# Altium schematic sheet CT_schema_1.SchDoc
size 703 x 687 mm
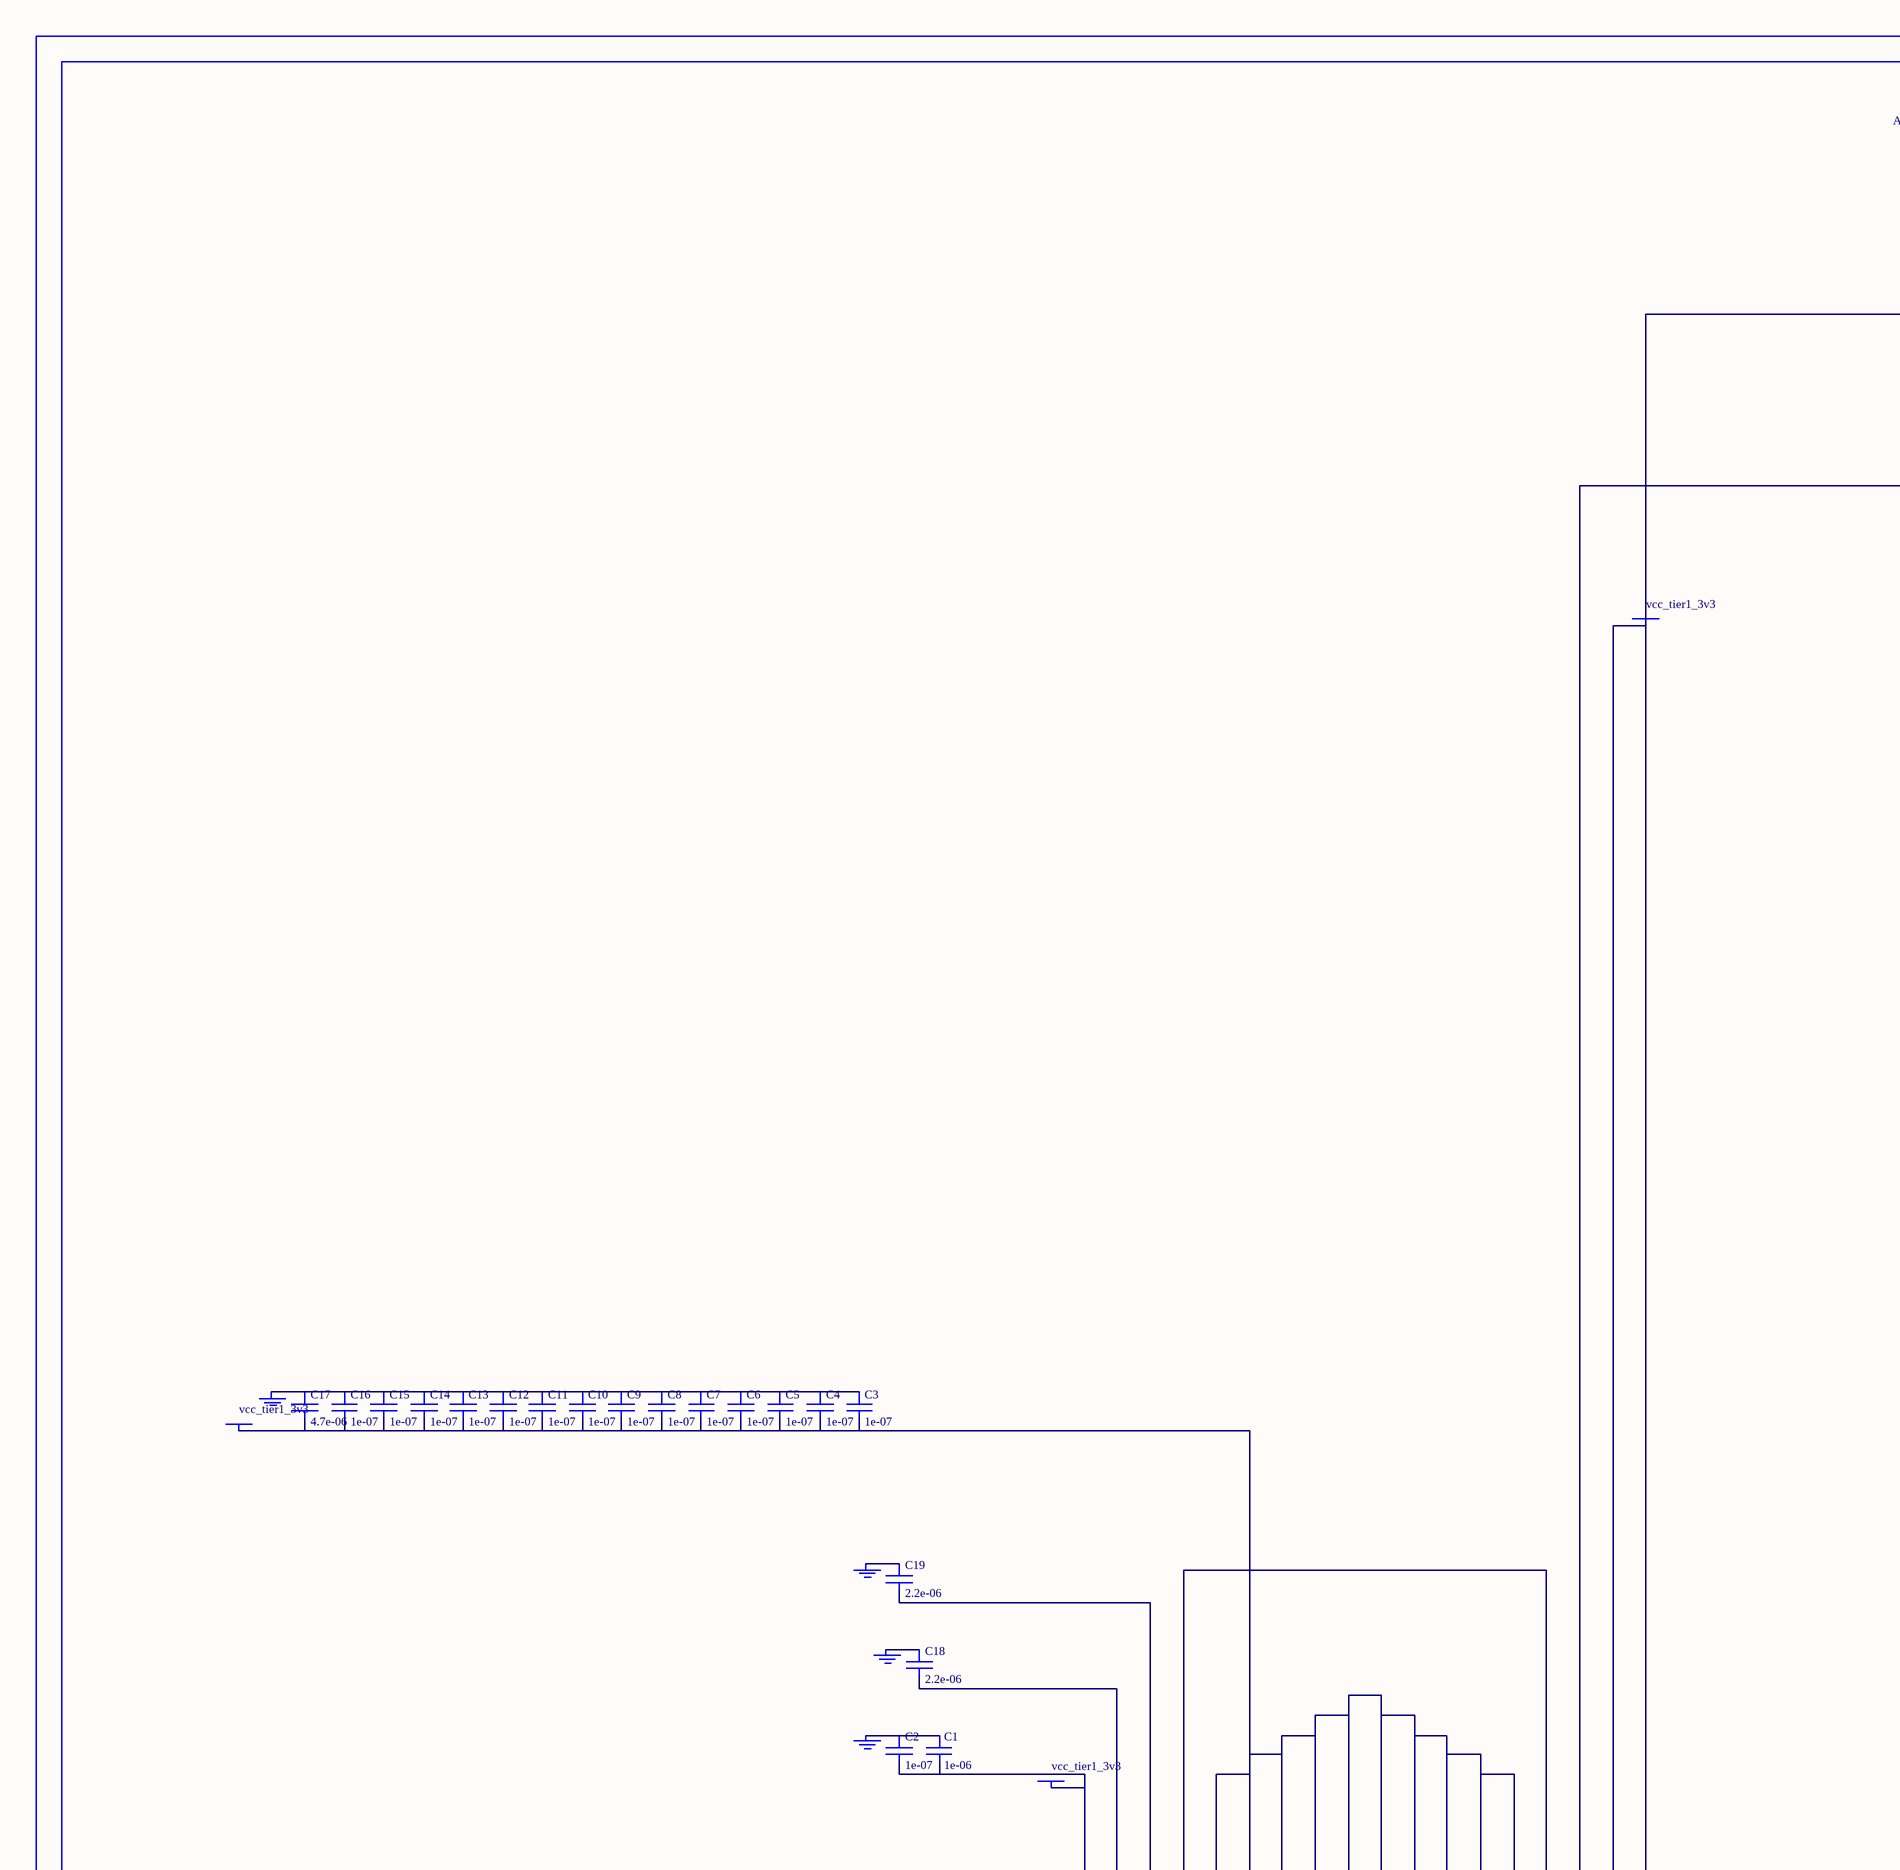
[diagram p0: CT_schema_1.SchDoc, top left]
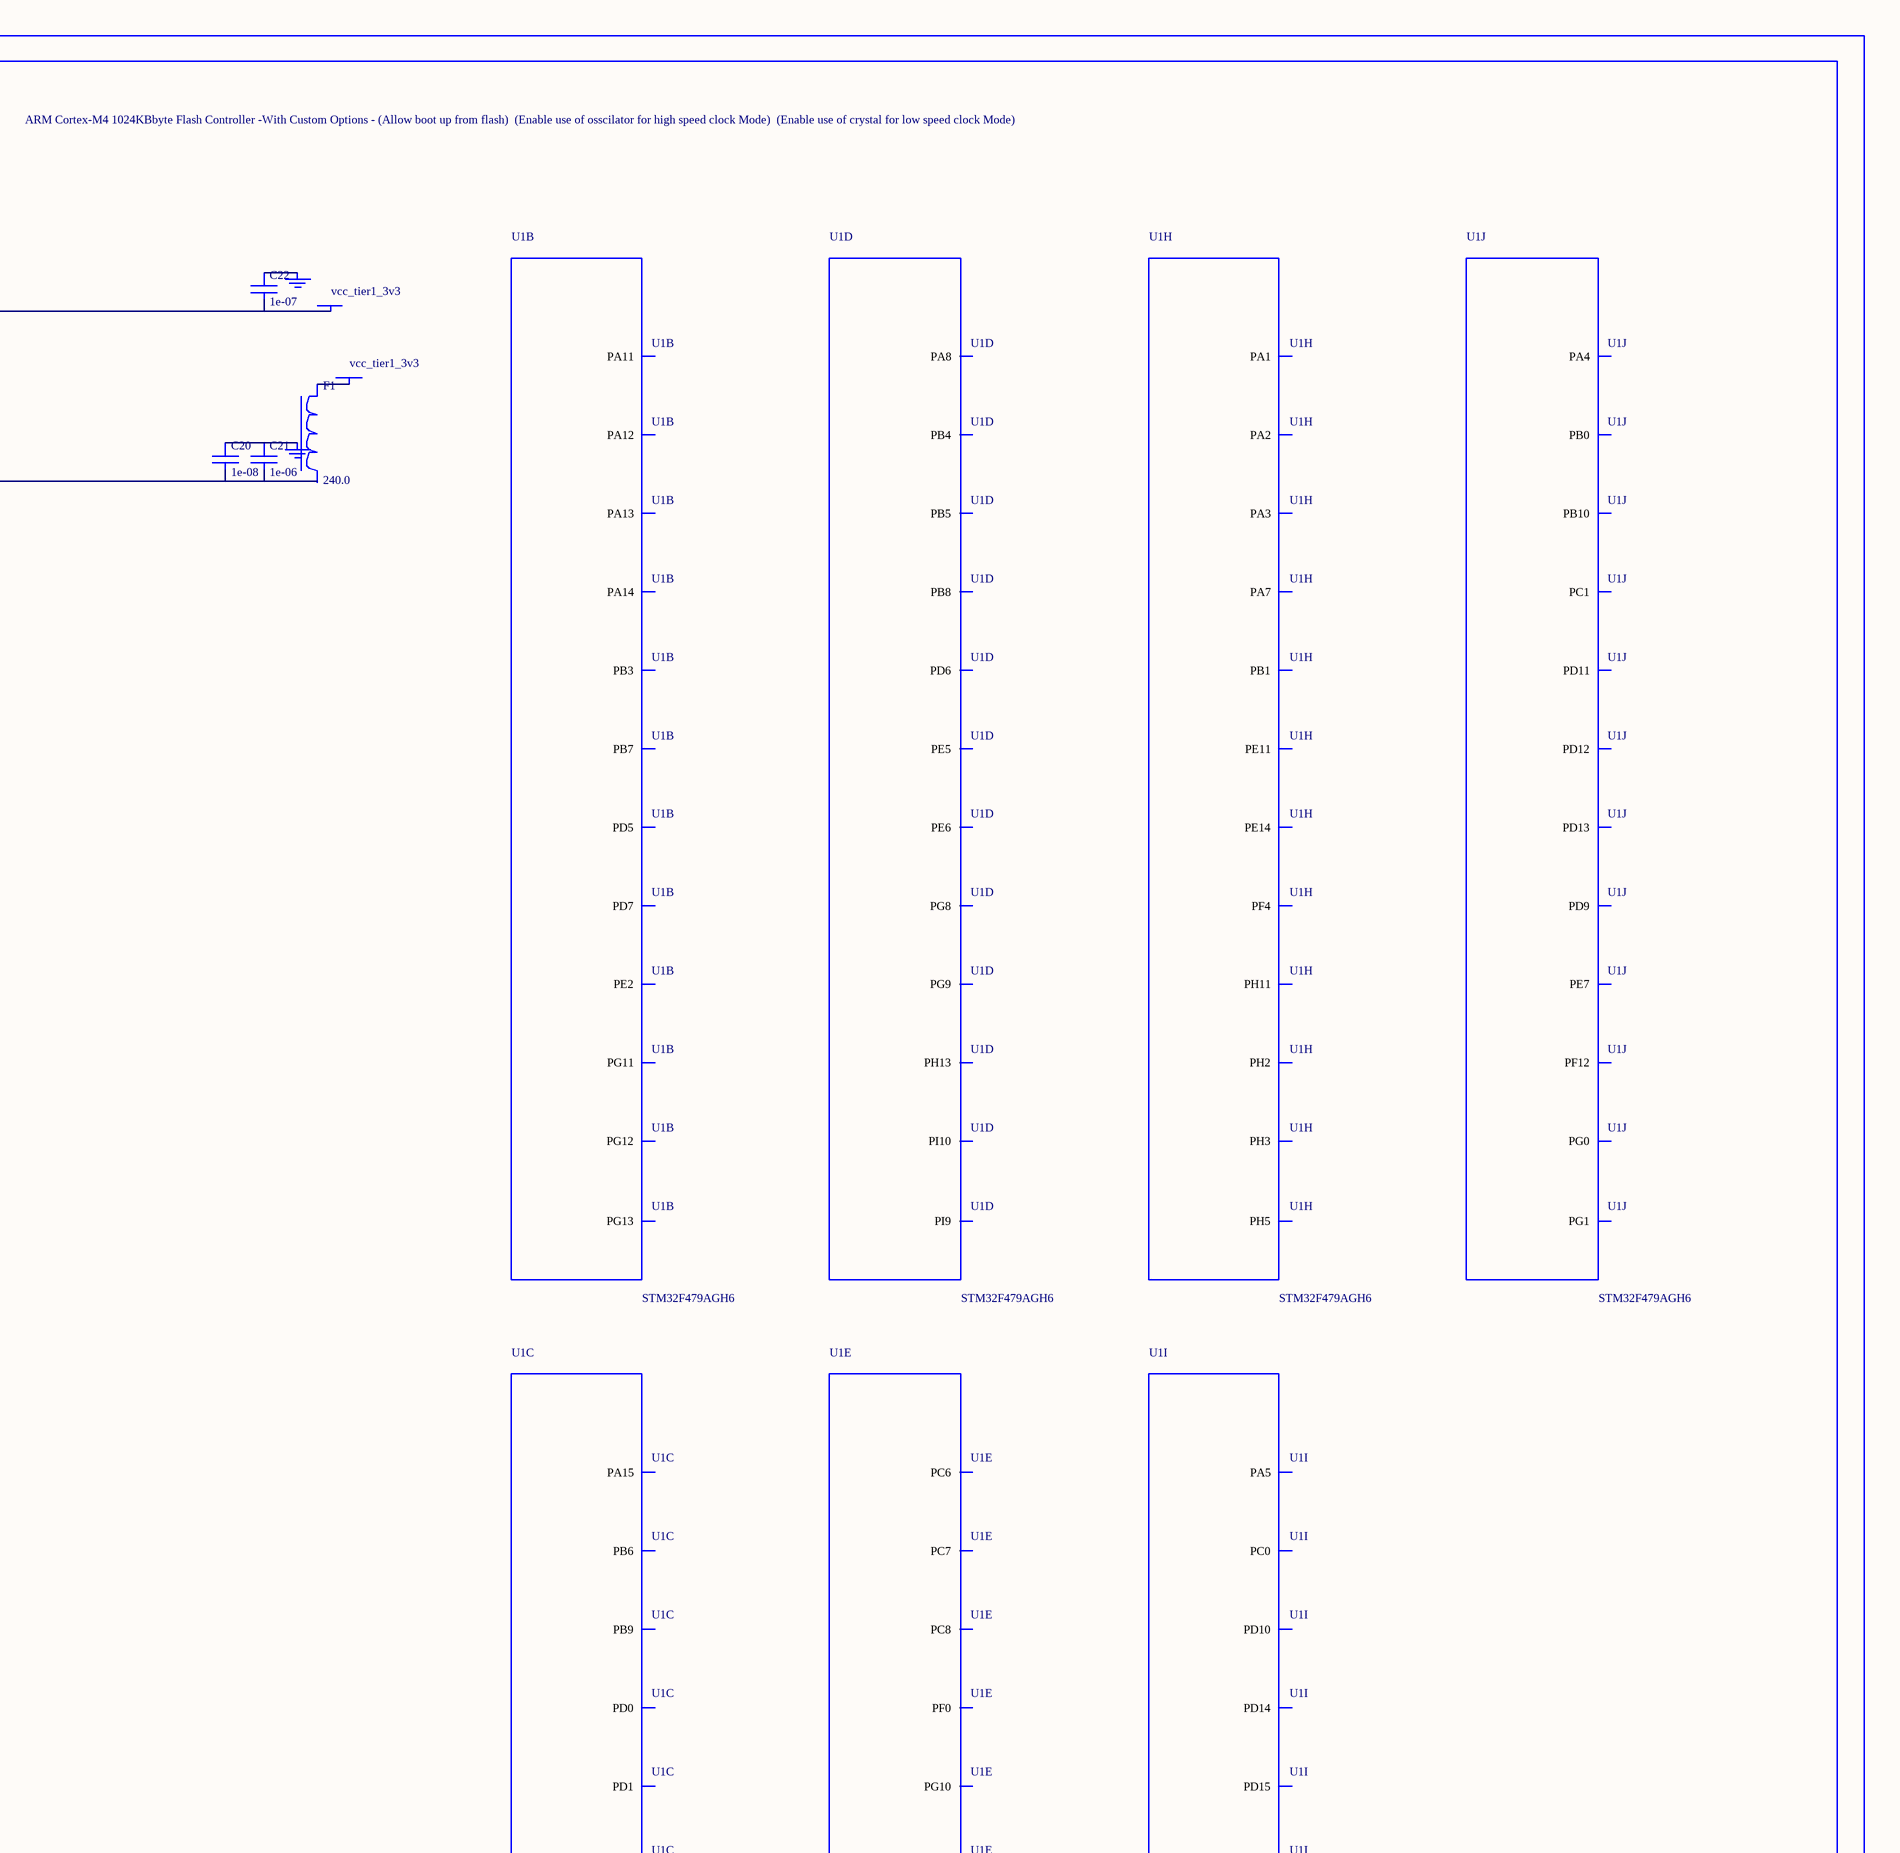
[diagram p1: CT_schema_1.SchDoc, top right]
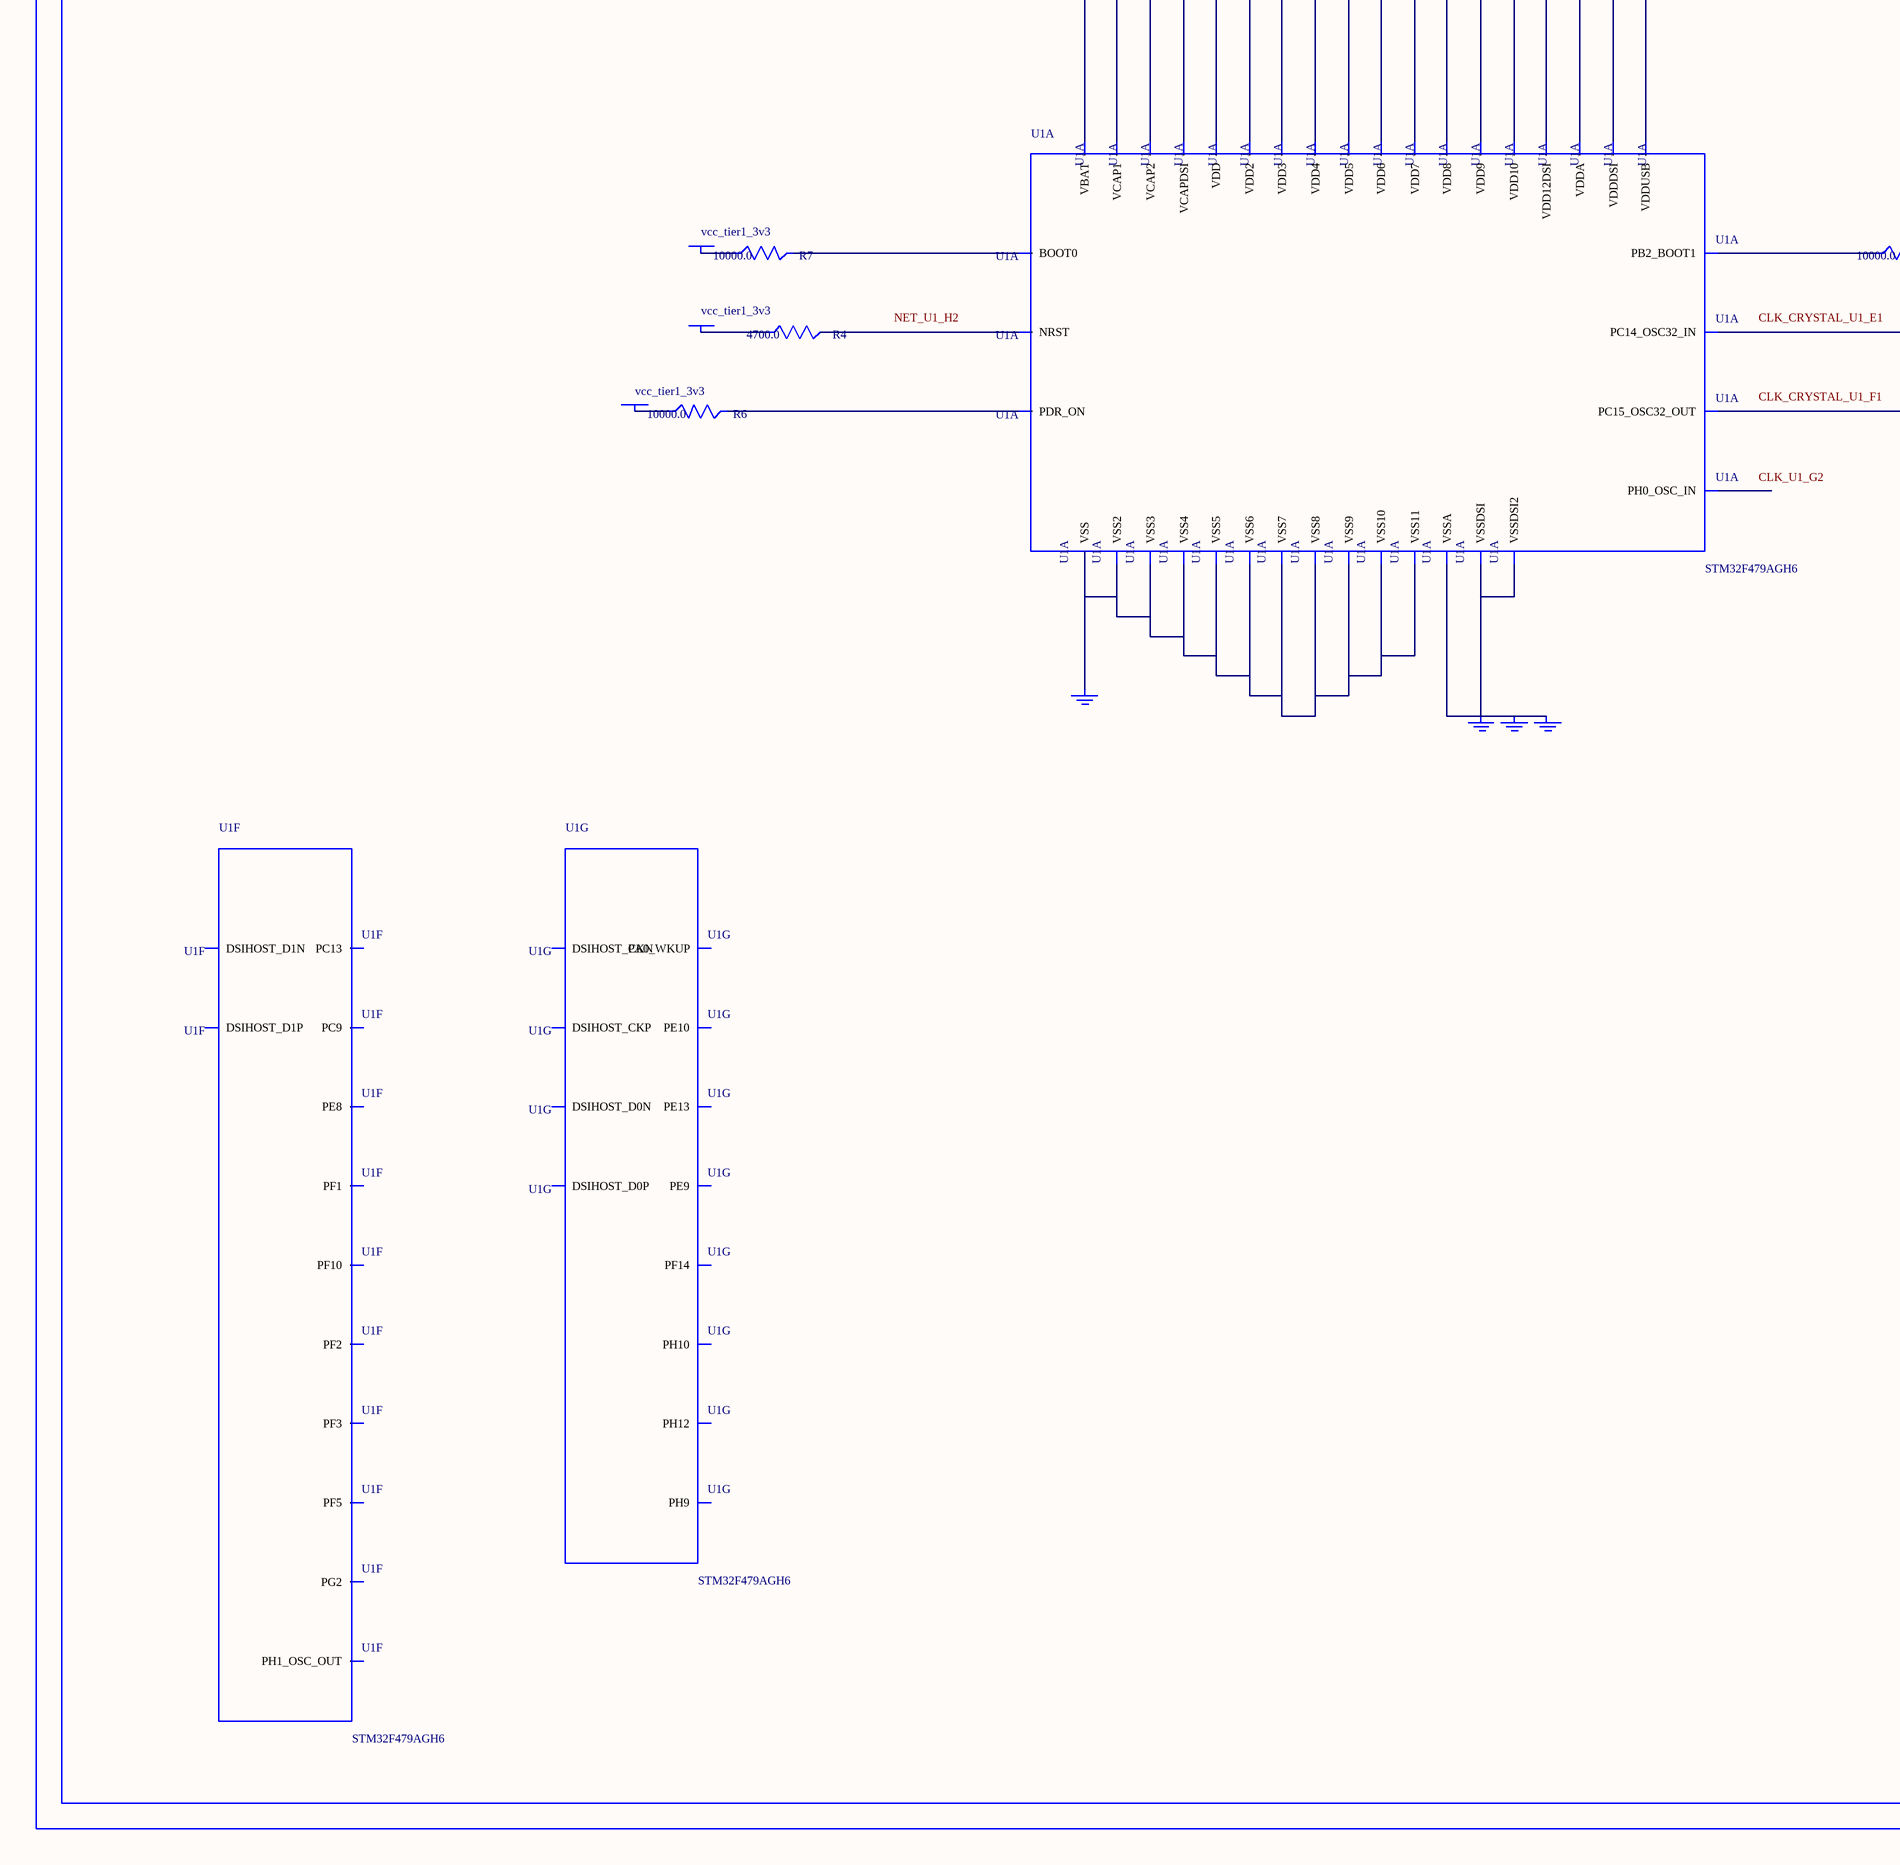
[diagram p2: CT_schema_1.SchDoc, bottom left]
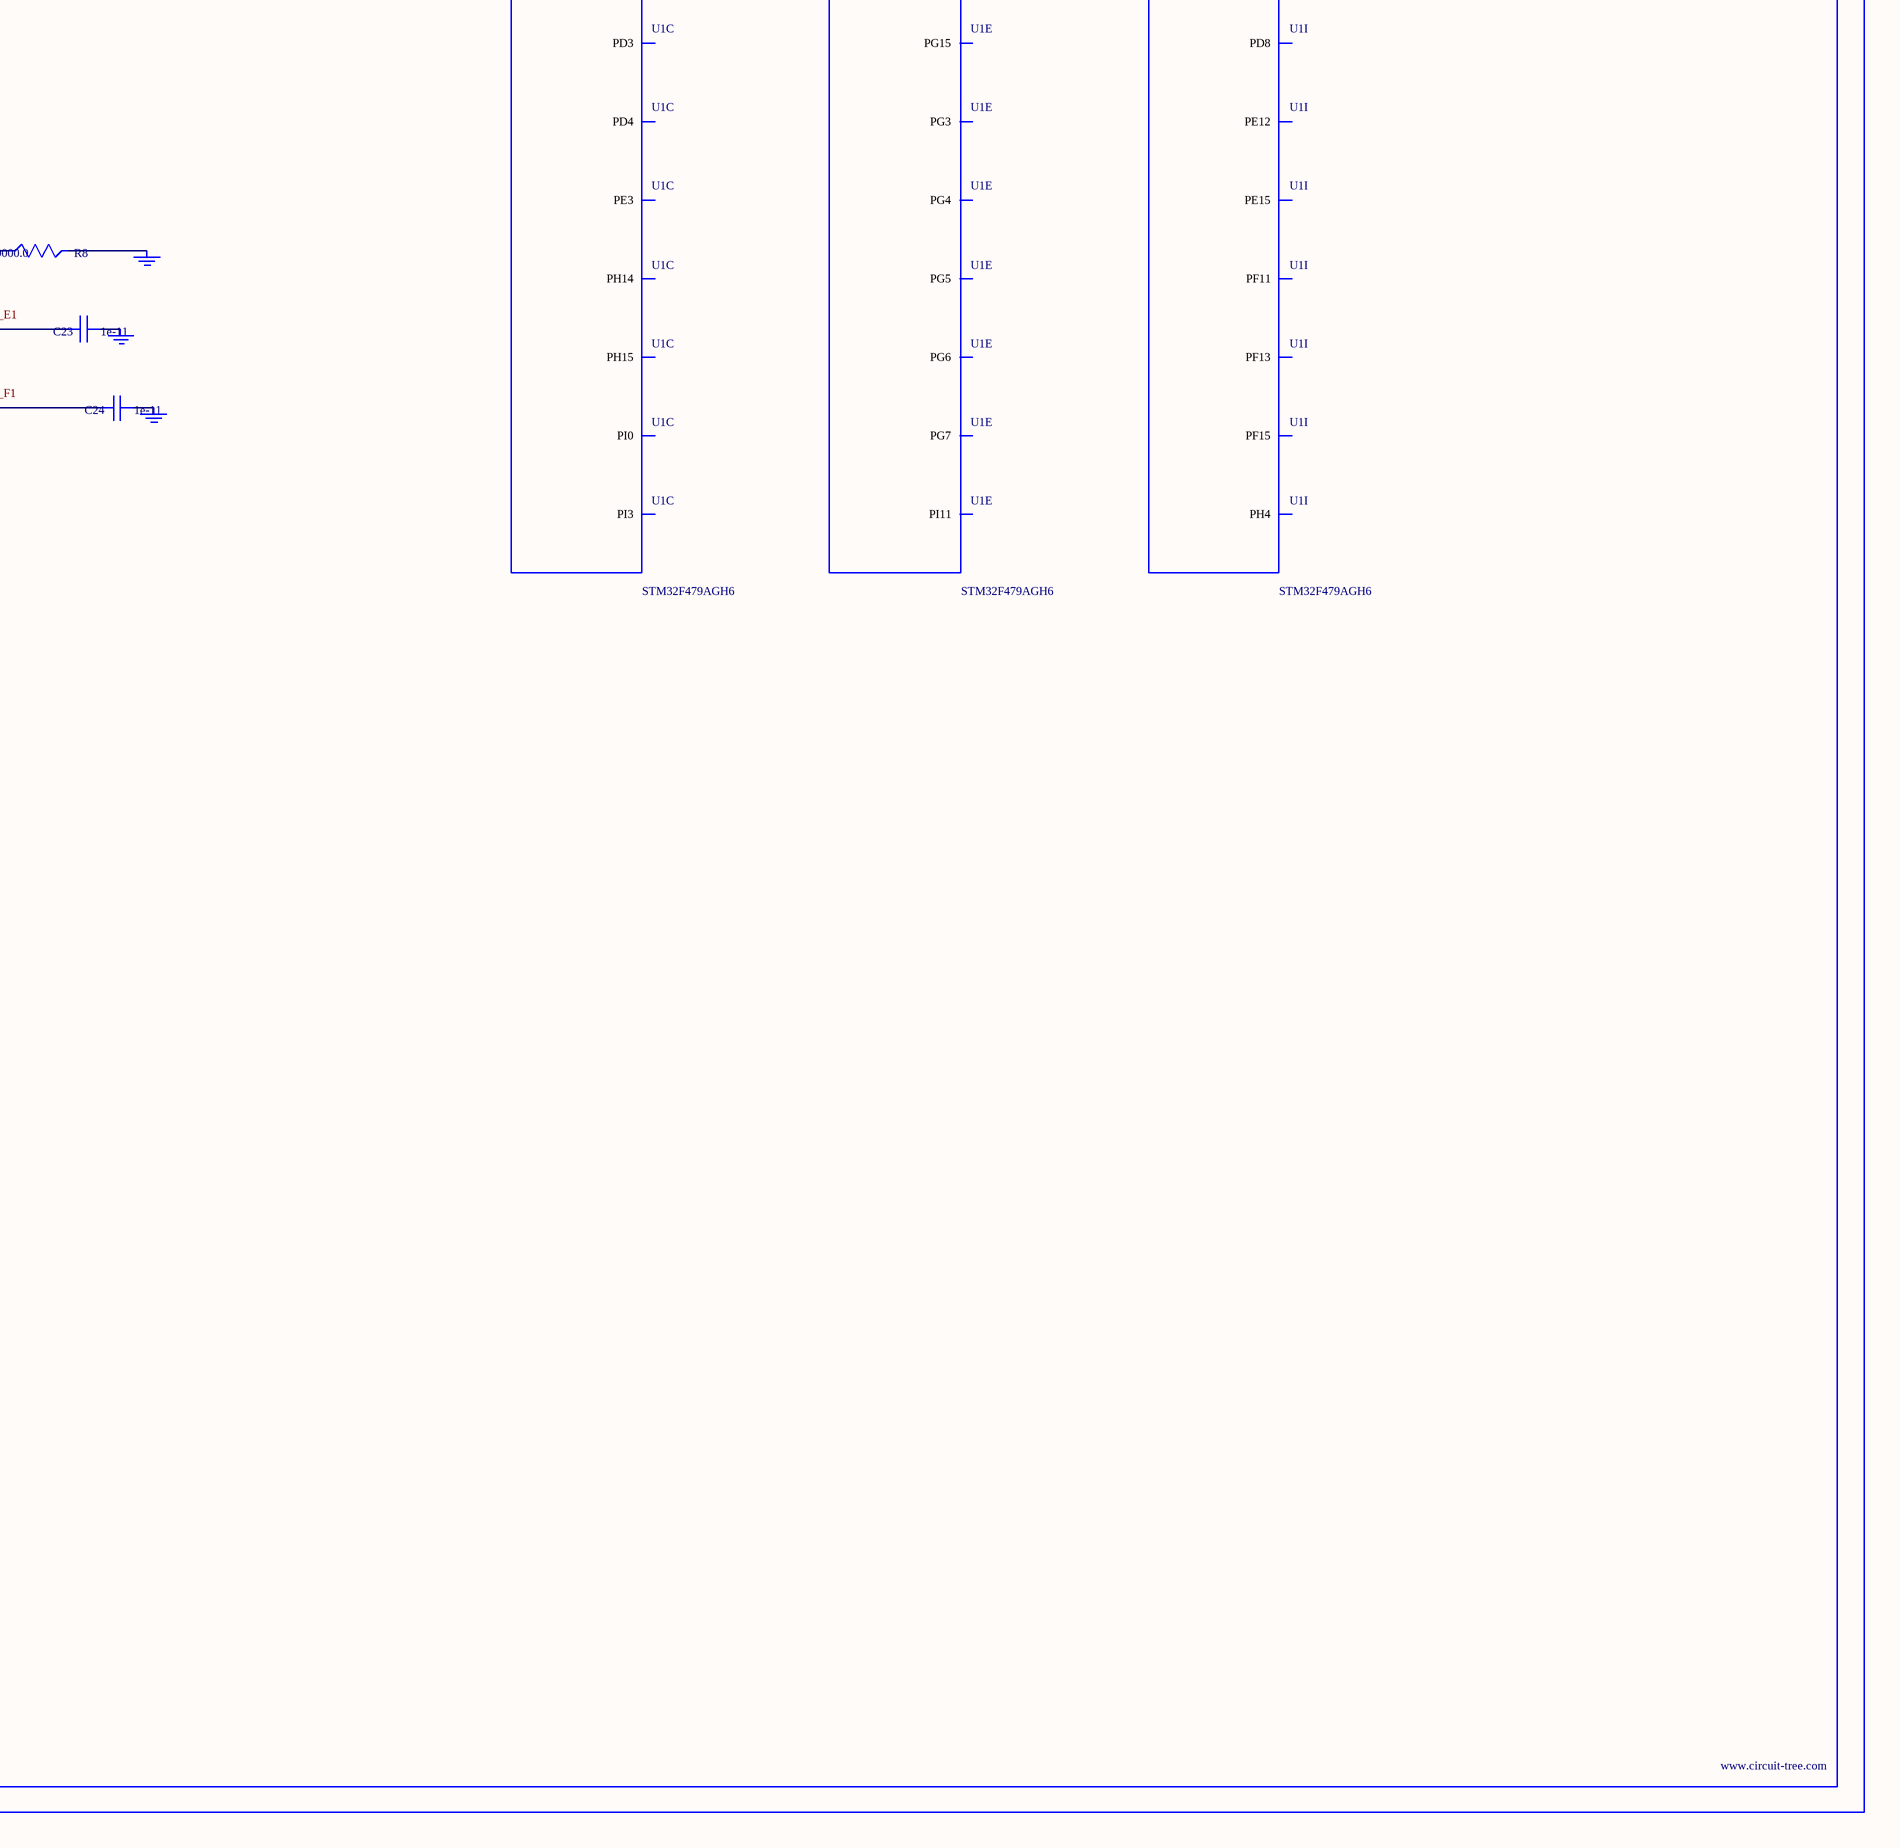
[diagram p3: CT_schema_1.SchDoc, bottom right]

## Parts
BORDER0  (no value)
C1  1e-06  [C0603]
C2  1e-07  [C0603]
C3  1e-07  [C0603]
C4  1e-07  [C0603]
C5  1e-07  [C0603]
C6  1e-07  [C0603]
C7  1e-07  [C0603]
C8  1e-07  [C0603]
C9  1e-07  [C0603]
C10  1e-07  [C0603]
C11  1e-07  [C0603]
C12  1e-07  [C0603]
C13  1e-07  [C0603]
C14  1e-07  [C0603]
C15  1e-07  [C0603]
C16  1e-07  [C0603]
C17  4.7e-06  [C0603]
C18  2.2e-06  [C0603]
C19  2.2e-06  [C0603]
C20  1e-08  [C0603]
C21  1e-06  [C0603]
C22  1e-07  [C0603]
C23  1e-11  [C0402]
C24  1e-11  [C0402]
F1  240.0  [L0603]
GND_INSTANCE_0_0  (no value)
GND_INSTANCE_0_1  (no value)
GND_INSTANCE_0_2  (no value)
GND_INSTANCE_0_3  (no value)
GND_INSTANCE_0_4  (no value)
GND_INSTANCE_0_5  (no value)
GND_INSTANCE_0_6  (no value)
GND_INSTANCE_0_7  (no value)
GND_INSTANCE_0_8  (no value)
GND_INSTANCE_0_9  (no value)
GND_INSTANCE_0_10  (no value)
GND_INSTANCE_0_11  (no value)
GND_INSTANCE_0_12  (no value)
POWER_INSTANCE_0_0  vcc_tier1_3v3
POWER_INSTANCE_0_1  vcc_tier1_3v3
POWER_INSTANCE_0_2  vcc_tier1_3v3
POWER_INSTANCE_0_3  vcc_tier1_3v3
POWER_INSTANCE_0_4  vcc_tier1_3v3
POWER_INSTANCE_0_5  vcc_tier1_3v3
POWER_INSTANCE_0_6  vcc_tier1_3v3
POWER_INSTANCE_0_7  vcc_tier1_3v3
R4  4700.0  [R0603]
R6  10000.0  [R0603]
R7  10000.0  [R0603]
R8  10000.0  [R0603]
U1  STM32F479AGH6  [UFBGA169]  (parts A,B,C,D,E,F,G,H,I,J of 12)

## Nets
NetC1_1: C1.1 C2.1 GND_INSTANCE_0_0.0(GND)
NetC1_2: C1.2 C2.2 POWER_INSTANCE_0_0.0(PWR) U1.E5(VBAT)
NetC3_1: C3.1 C4.1 C5.1 C6.1 C7.1 C8.1 C9.1 C10.1 C11.1 C12.1 C13.1 C14.1 C15.1 C16.1 C17.1 GND_INSTANCE_0_2.0(GND)
NetC3_2: C3.2 C4.2 C5.2 C6.2 C7.2 C8.2 C9.2 C10.2 C11.2 C12.2 C13.2 C14.2 C15.2 C16.2 C17.2 POWER_INSTANCE_0_2.0(PWR) U1.D3(VDD2) U1.D10(VDD) U1.F4(VDD3) U1.F7(VDD4) U1.G8(VDD5) U1.J4(VDD6) U1.K6(VDD8) U1.K10(VDD7) U1.L6(VDD9) U1.L9(VDD10)
NetC18_1: C18.1 GND_INSTANCE_0_3.0(GND)
NetC18_2: C18.2 U1.N9(VCAP1)
NetC19_1: C19.1 GND_INSTANCE_0_4.0(GND)
NetC19_2: C19.2 U1.D12(VCAP2)
NetC20_1: C20.1 C21.1 GND_INSTANCE_0_1.0(GND)
NetC20_2: C20.2 C21.2 U1.J3(VDDA)
NetC22_1: C22.1 GND_INSTANCE_0_5.0(GND)
NetC22_2: C22.2 POWER_INSTANCE_0_4.0(PWR) POWER_INSTANCE_0_6.0(PWR) U1.G11(VDDUSB) U1.K13(VDDDSI)
NetC23_1: C23.1 GND_INSTANCE_0_7.0(GND)
NetC23_2: C23.2 U1.E1(PC14_OSC32_IN)
NetC24_1: C24.1 GND_INSTANCE_0_8.0(GND)
NetC24_2: C24.2 U1.F1(PC15_OSC32_OUT)
NetF1_1: F1.1 POWER_INSTANCE_0_1.0(PWR)
NetGND_INSTANCE_0_6_0: GND_INSTANCE_0_6.0(GND) R8.2
NetGND_INSTANCE_0_9_0: GND_INSTANCE_0_9.0(GND) GND_INSTANCE_0_10.0(GND) GND_INSTANCE_0_11.0(GND) U1.H11(VSSDSI) U1.J2(VSSA) U1.K11(VSSDSI2)
NetGND_INSTANCE_0_12_0: GND_INSTANCE_0_12.0(GND) U1.D11(VSS) U1.E3(VSS2) U1.F5(VSS3) U1.F8(VSS4) U1.G7(VSS5) U1.G9(VSS6) U1.J1(VSS7) U1.J6(VSS9) U1.J7(VSS10) U1.J10(VSS8) U1.M9(VSS11)
NetPOWER_INSTANCE_0_3_0: POWER_INSTANCE_0_3.0(PWR) R6.1
NetPOWER_INSTANCE_0_5_0: POWER_INSTANCE_0_5.0(PWR) R7.1
NetPOWER_INSTANCE_0_7_0: POWER_INSTANCE_0_7.0(PWR) R4.1
NetR4_2: R4.2 U1.H2(NRST)
NetR6_2: R6.2 U1.C3(PDR_ON)
NetR7_2: R7.2 U1.A5(BOOT0)
NetR8_1: R8.1 U1.L5(PB2_BOOT1)
NetU1_J11: U1.J11(VDD12DSI) U1.K12(VCAPDSI)

Not connected (* = marked no-connect by the designer): F1 2; U1 A6(PG13) A7(PG12) A8(PD7) A10(PA14) A11(PA13) A12(PA12) A13(PA11) B2(PE2) B4(PB7) B5(PB3) B6(PG11) B7(PD5) B10(PI3) B11(PA15) B13(PI0) C1(PE3) C4(PB9) C5(PB6) C6(PD4) C7(PD1) C8(PD3) C9(PD0) C12(PH15) C13(PH14) D1(PE5) D2(PE6) D4(PB8) D5(PB5) D6(PB4) D7(PD6) D8(PA8) D9(PH13) D13(PG8) E2(PI9) E4(PI10) E6(PG9) E7(PG10) E10(PC8) E11(PG7) E12(PG5) E13(PG4) F2(PI11) F3(PF0) F6(PG15) F9(PC6) F10(PC7) F11(PG6) F12(PG3) F13(PG2) G1(PH1_OSC_OUT) G2(PH0_OSC_IN) G3(PF1) G4(PC13) G5(PF2) G6(PE8) G10(PC9) G12(DSIHOST_D1P) G13(DSIHOST_D1N) H1(PF10) H3(PF5) H4(PF3) H5(PF14) H6(PE9) H7(PE10) H9(PH9) H10(PH12) H12(DSIHOST_CKP) H13(DSIHOST_CKN) J5(PA0_WKUP) J8(PE13) J9(PH10) J12(DSIHOST_D0P) J13(DSIHOST_D0N) K1(PA1) K2(PA2) K3(PA3) K4(PA7) K5(PB1) K7(PE11) K8(PE14) K9(PH11) L1(PH3) L2(PH2) L3(PH5) L4(PF4) L7(PE12) L8(PE15) L10(PD8) L11(PD10) L12(PD14) L13(PD15) M1(PC0) M2(PH4) M3(PA5) M4(PF13) M5(PF11) M6(PF15) M7(PG1) M8(PB10) M10(PD9) M11(PD11) M12(PD13) M13(PD12) N1(PC1) N2(PA4) N4(PB0) N5(PF12) N6(PG0) N7(PE7)

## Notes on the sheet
- Labels drawn without touching a wire or pin: CLK_CRYSTAL_U1_E1, CLK_CRYSTAL_U1_F1, CLK_U1_G2, NET_U1_H2

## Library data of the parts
BORDER0 = BORDER_PAGE0
C1 C21 = C0603C105K3RACTU
C2-C16 C22 = 06035C104K4Z2A
C17 = GRM188R6YA475KE15D
C18 C19 = C0603C225K8RACTU
C20 = 06035C103K4Z2A
C23 C24 = C0402C100K3GACTU
F1 = Z0603C241ASMST
GND_INSTANCE_0_0-GND_INSTANCE_0_12 = GND
POWER_INSTANCE_0_0-POWER_INSTANCE_0_7 = PWR
R4 = RC0603JR-074K7L
R6-R8 = RC0603JR-0710KL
